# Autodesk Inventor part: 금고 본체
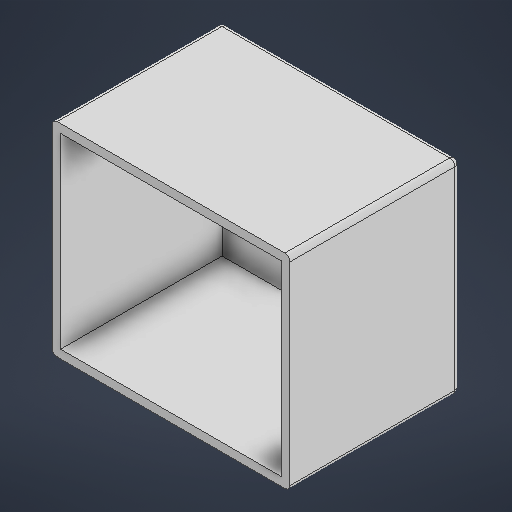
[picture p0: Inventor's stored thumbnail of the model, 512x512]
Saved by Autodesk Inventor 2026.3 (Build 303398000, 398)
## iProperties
Created: 2026-08
Part Number: 금고 본체
Material: 일반
Document SubType Name: Modeling
Designer: chang
Density: 1 g/cm^3
Appearance: 기본값
Author: chang
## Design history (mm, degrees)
sketch "스케치1"
  geometry: L1 (0, 0)-(0, 120); L2 (0, 120)-(140, 120); L3 (140, 120)-(140, 0); L4 (140, 0)-(0, 0)
  constraints: 8 end point, 3 perpendicular, 1 vertical
  dimensions: "d0" = 120 distance of L1.start L1.end; "d1" = 140 distance of L1.end L2.end
extrude "돌출1" new body sketch "스케치1" distance "d2" = 100; taper "d3" = 0 deg
feature "쉘1" dims "d4" = 5
feature "면 모깎기1" dims "d5" = 3
feature "면 모깎기2" dims "d6" = 3
feature "면 모깎기3" dims "d7" = 3
feature "면 모깎기4" dims "d8" = 3
node "솔리드1"
